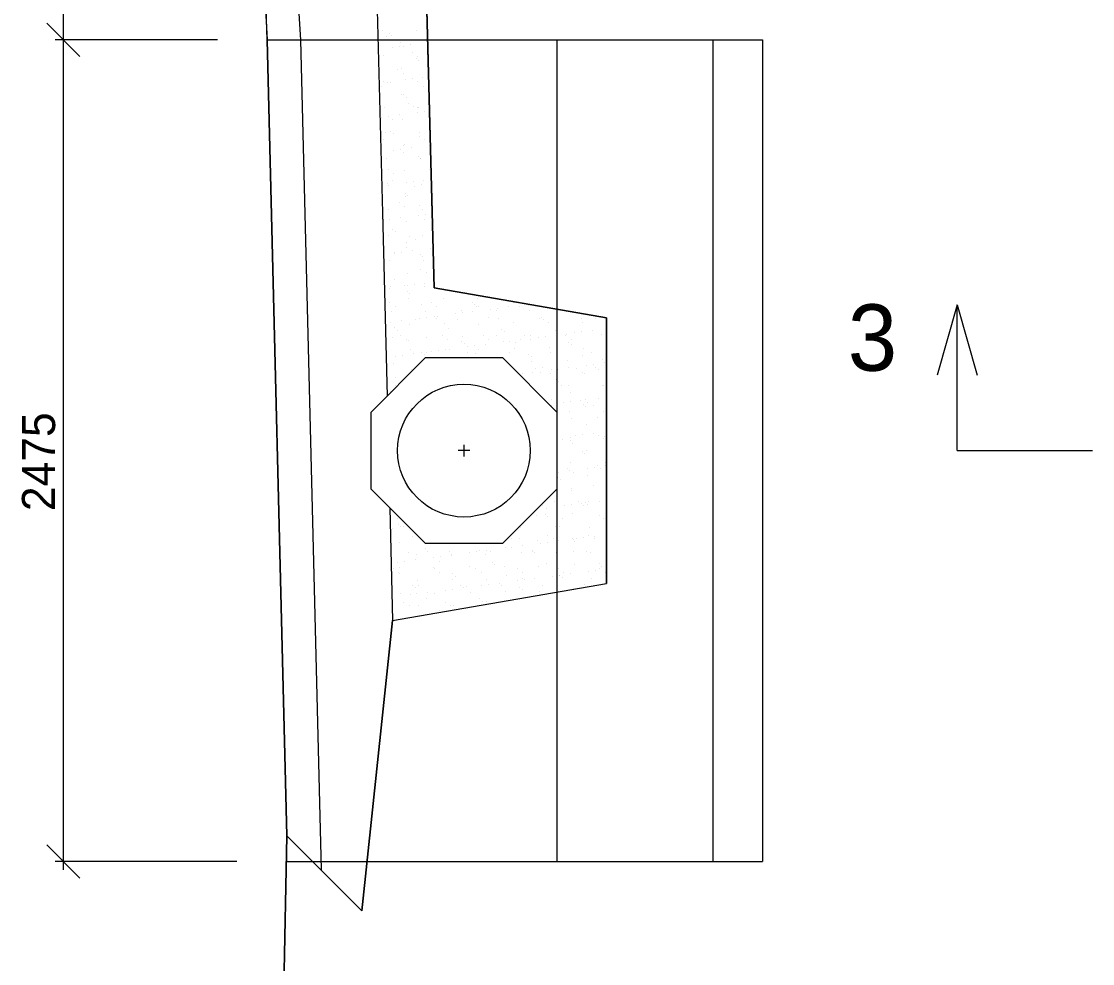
# Model space of a CAD drawing. Extents: x -2363 to 18637, y 14070 to 28920.
# Drawn here: x -595 to 2634, y 19057 to 21895 of the extents above; entities that cross this region are included whole.
import ezdxf

# ---------------------------------------------------------------- set-up
doc = ezdxf.new("R2010")
doc.units = 0
for name, color, linetype in [('KÓTY', 7, 'Continuous'), ('OBRYS', 7, 'Continuous'), ('SJEZD', 7, 'Continuous'), ('ŠRAFY', 7, 'Continuous')]:
    doc.layers.add(name, color=color, linetype=linetype)

# ---------------------------------------------------------------- blocks, each defined once
blk = doc.blocks.new('_ARCHTICK')
blk.add_lwpolyline([(-0.5, -0.5), (0.5, 0.5)])

msp = doc.modelspace()

# ---------------------------------------------------------------- linework, layer by layer
at = {"layer": 'KÓTY'}
for p, q in [((-468.1, 21814.7), (-468.1, 22364.7)), ((-468.1, 19339.7), (-468.1, 21864.7)), ((-3.8, 21839.7), (-493.1, 21839.7)), ((-3.8, 21839.7), (-493.1, 21839.7)), ((2225.7, 21041.5), (2165.7, 20829)), ((2225.7, 20602.2), (2225.7, 21041.5)), ((2225.7, 21041.5), (2285.7, 20829)), ((2225.7, 20602.2), (2633.8, 20602.2)), ((54.3, 19364.7), (-493.1, 19364.7))]:
    msp.add_line(p, q, dxfattribs=at)
at = {"layer": 'OBRYS'}
for p, q in [((649.6, 21092.9), (495.9, 26839.7)), ((146.2, 21839.7), (35.9, 25339.7)), ((205.8, 19441.7), (146.2, 21839.7)), ((1169.1, 21002.2), (649.6, 21092.9)), ((1169.1, 20202.2), (1169.1, 21002.2)), ((524.1, 20090.3), (1169.1, 20202.2)), ((431.3, 19216.3), (524.1, 20090.3)), ((175.8, 17970), (205.8, 19441.7)), ((205.8, 19441.7), (431.3, 19216.3))]:
    msp.add_line(p, q, dxfattribs=at)
msp.add_circle((739.1, 20602.2), 200, dxfattribs=at)
at = {"layer": 'SJEZD'}
for p, q in [((495.9, 26839.7), (649.6, 21092.9)), ((375.9, 25715.5), (493.5, 21318.7)), ((216.1, 22342), (246.2, 21839.7)), ((116.2, 22339.7), (146.2, 21839.7)), ((146.2, 21839.7), (205.8, 19441.7)), ((146.2, 21839.7), (1639.1, 21839.7)), ((246.2, 21839.7), (308.4, 19339.2)), ((1019.1, 21839.7), (1019.1, 19364.7)), ((1489.1, 21839.7), (1489.1, 19364.7)), ((1639.1, 21839.7), (1639.1, 19364.7)), ((493.5, 21318.7), (507.3, 20766.3)), ((649.6, 21092.9), (1169.1, 21002.2)), ((1169.1, 21002.2), (1169.1, 20202.2)), ((459.1, 20718.2), (623.2, 20882.2)), ((623.2, 20882.2), (855.1, 20882.2)), ((855.1, 20882.2), (1019.1, 20718.2)), ((459.1, 20486.3), (459.1, 20718.2)), ((1019.1, 20718.2), (1019.1, 20486.3)), ((756.5, 20602.2), (721.8, 20602.2)), ((739.1, 20619.6), (739.1, 20584.9)), ((623.2, 20322.2), (459.1, 20486.3)), ((1019.1, 20486.3), (855.1, 20322.2)), ((515.6, 20429.8), (524.1, 20090.3)), ((855.1, 20322.2), (623.2, 20322.2)), ((524.1, 20090.3), (1169.1, 20202.2)), ((524.1, 20090.3), (431.3, 19216.3)), ((205.8, 19441.7), (175.8, 17970)), ((205.8, 19441.7), (431.3, 19216.3)), ((204.3, 19364.7), (1639.1, 19364.7))]:
    msp.add_line(p, q, dxfattribs=at)
msp.add_circle((739.1, 20602.2), 200, dxfattribs=at)
at = {"layer": 'ŠRAFY'}
for p, q in [((493.1, 21868.1), (493.1, 21868.1)), ((513.8, 21859), (513.8, 21859)), ((595.4, 21867.6), (595.4, 21867.6)), ((506.8, 21849.6), (506.8, 21849.6)), ((521.1, 21852.2), (521.1, 21852.2)), ((523.7, 21838.8), (523.7, 21838.8)), ((547.2, 21830.6), (547.2, 21830.6)), ((578.4, 21825), (578.4, 21825)), ((525.1, 21818), (525.1, 21818)), ((545.9, 21820.7), (545.9, 21820.7)), ((555.9, 21820.4), (555.9, 21820.4)), ((584.4, 21800.1), (584.4, 21800.1)), ((495.6, 21791), (495.6, 21791)), ((595.8, 21783.9), (595.8, 21783.9)), ((597.9, 21790.5), (597.9, 21790.5)), ((603.1, 21777.1), (603.1, 21777.1)), ((482.9, 21742), (482.9, 21742)), ((539.1, 21749.4), (539.1, 21749.4)), ((549.7, 21753.5), (549.7, 21753.5)), ((556, 21738.7), (556, 21738.7)), ((492.1, 21699.8), (492.1, 21699.8)), ((498.1, 21714), (498.1, 21714)), ((507.6, 21712.1), (507.6, 21712.1)), ((517.7, 21710.1), (517.7, 21710.1)), ((562, 21719.3), (562, 21719.3)), ((582.8, 21722), (582.8, 21722)), ((600.4, 21713.5), (600.4, 21713.5)), ((615.3, 21726.3), (615.3, 21726.3)), ((616.7, 21700), (616.7, 21700)), ((552.2, 21676.4), (552.2, 21676.4)), ((557.5, 21673.6), (557.5, 21673.6)), ((564.9, 21666.9), (564.9, 21666.9)), ((500.6, 21636.9), (500.6, 21636.9)), ((571.4, 21649.3), (571.4, 21649.3)), ((588.3, 21638.5), (588.3, 21638.5)), ((599.7, 21635), (599.7, 21635)), ((603, 21636.4), (603, 21636.4)), ((491.2, 21606.4), (491.2, 21606.4)), ((512, 21609.1), (512, 21609.1)), ((524.4, 21599.6), (524.4, 21599.6)), ((544.5, 21613.4), (544.5, 21613.4)), ((554.7, 21599.4), (554.7, 21599.4)), ((598.8, 21620.6), (598.8, 21620.6)), ((619.7, 21623.3), (619.7, 21623.3)), ((496, 21538.1), (496, 21538.1)), ((503.2, 21559.8), (503.2, 21559.8)), ((519.2, 21563.4), (519.2, 21563.4)), ((526.6, 21556.6), (526.6, 21556.6)), ((603.7, 21549.1), (603.7, 21549.1)), ((605.5, 21559.3), (605.5, 21559.3)), ((620.6, 21538.3), (620.6, 21538.3)), ((528, 21507.7), (528, 21507.7)), ((548.9, 21510.4), (548.9, 21510.4)), ((557.2, 21522.3), (557.2, 21522.3)), ((561.4, 21524.8), (561.4, 21524.8)), ((581.4, 21514.7), (581.4, 21514.7)), ((635.7, 21521.9), (635.7, 21521.9)), ((505.7, 21482.7), (505.7, 21482.7)), ((556.7, 21499.4), (556.7, 21499.4)), ((601.2, 21488.3), (601.2, 21488.3)), ((608, 21482.2), (608, 21482.2)), ((608.6, 21481.5), (608.6, 21481.5)), ((511.4, 21448.7), (511.4, 21448.7)), ((528.3, 21438), (528.3, 21438)), ((559.8, 21445.2), (559.8, 21445.2)), ((636, 21448.9), (636, 21448.9)), ((508.2, 21405.7), (508.2, 21405.7)), ((523.2, 21414.5), (523.2, 21414.5)), ((564.9, 21409), (564.9, 21409)), ((585.7, 21411.7), (585.7, 21411.7)), ((610.5, 21405.2), (610.5, 21405.2)), ((618.3, 21416), (618.3, 21416)), ((510.6, 21401.8), (510.6, 21401.8)), ((563, 21378), (563, 21378)), ((589, 21399.3), (589, 21399.3)), ((543.7, 21348.5), (543.7, 21348.5)), ((562.3, 21368.2), (562.3, 21368.2)), ((570.3, 21371.3), (570.3, 21371.3)), ((510.7, 21328.6), (510.7, 21328.6)), ((560.6, 21337.8), (560.6, 21337.8)), ((601.8, 21310.3), (601.8, 21310.3)), ((605.1, 21339.4), (605.1, 21339.4)), ((613, 21328.1), (613, 21328.1)), ((622.6, 21313), (622.6, 21313)), ((494.1, 21296.1), (494.1, 21296.1)), ((496.8, 21298.9), (496.8, 21298.9)), ((515, 21298.8), (515, 21298.8)), ((547.5, 21303.1), (547.5, 21303.1)), ((564.8, 21291.1), (564.8, 21291.1)), ((621.3, 21299.1), (621.3, 21299.1)), ((513.2, 21251.5), (513.2, 21251.5)), ((524.7, 21267.8), (524.7, 21267.8)), ((532.1, 21261.1), (532.1, 21261.1)), ((576.1, 21248.4), (576.1, 21248.4)), ((615.6, 21251), (615.6, 21251)), ((566.9, 21229.2), (566.9, 21229.2)), ((567.3, 21214), (567.3, 21214)), ((592.9, 21237.6), (592.9, 21237.6)), ((638.7, 21211.6), (638.7, 21211.6)), ((529.1, 21198.7), (529.1, 21198.7)), ((531, 21197.4), (531, 21197.4)), ((551.8, 21200.1), (551.8, 21200.1)), ((584.3, 21204.4), (584.3, 21204.4)), ((606.7, 21192.7), (606.7, 21192.7)), ((614.1, 21185.9), (614.1, 21185.9)), ((515.8, 21174.4), (515.8, 21174.4)), ((608.4, 21148.2), (608.4, 21148.2)), ((618.1, 21173.9), (618.1, 21173.9)), ((500.7, 21137.2), (500.7, 21137.2)), ((528.6, 21118.9), (528.6, 21118.9)), ((569.8, 21136.9), (569.8, 21136.9)), ((625.2, 21137.5), (625.2, 21137.5)), ((513.6, 21091.5), (513.6, 21091.5)), ((518.3, 21097.4), (518.3, 21097.4)), ((561.4, 21098.5), (561.4, 21098.5)), ((567.9, 21098.7), (567.9, 21098.7)), ((568.4, 21082.5), (568.4, 21082.5)), ((588.7, 21101.4), (588.7, 21101.4)), ((620.6, 21096.9), (620.6, 21096.9)), ((621.2, 21105.7), (621.2, 21105.7)), ((572.4, 21059.9), (572.4, 21059.9)), ((575.8, 21075.7), (575.8, 21075.7)), ((677.1, 21061.2), (677.1, 21061.2)), ((779.4, 21060.7), (779.4, 21060.7)), ((516.1, 21047.8), (516.1, 21047.8)), ((520.8, 21020.3), (520.8, 21020.3)), ((533, 21037.1), (533, 21037.1)), ((610.6, 21043.8), (610.6, 21043.8)), ((623.1, 21019.8), (623.1, 21019.8)), ((640.7, 21048), (640.7, 21048)), ((657.5, 21037.3), (657.5, 21037.3)), ((731.2, 21023.7), (731.2, 21023.7)), ((733.3, 21016.9), (733.3, 21016.9)), ((765.2, 21048.3), (765.2, 21048.3)), ((765.8, 21021.2), (765.8, 21021.2)), ((770.7, 21042.4), (770.7, 21042.4)), ((778, 21035.7), (778, 21035.7)), ((782.1, 21037.5), (782.1, 21037.5)), ((820.1, 21028.3), (820.1, 21028.3)), ((835.9, 21025), (835.9, 21025)), ((840.9, 21031), (840.9, 21031)), ((873.5, 21035.3), (873.5, 21035.3)), ((889.8, 21048.5), (889.8, 21048.5)), ((906.7, 21037.7), (906.7, 21037.7)), ((927.8, 21042.5), (927.8, 21042.5)), ((933.1, 21038.9), (933.1, 21038.9)), ((938.2, 21024.5), (938.2, 21024.5)), ((517.9, 20988.5), (517.9, 20988.5)), ((550.4, 20992.8), (550.4, 20992.8)), ((593.7, 20998.4), (593.7, 20998.4)), ((604.8, 21000), (604.8, 21000)), ((625.6, 21002.7), (625.6, 21002.7)), ((650.4, 21007.3), (650.4, 21007.3)), ((657.8, 21000.6), (657.8, 21000.6)), ((658.1, 21007), (658.1, 21007)), ((712.4, 21014.1), (712.4, 21014.1)), ((718.3, 20998.6), (718.3, 20998.6)), ((812.8, 21003.8), (812.8, 21003.8)), ((842.8, 20998.8), (842.8, 20998.8)), ((889.9, 20987.5), (889.9, 20987.5)), ((967.4, 20999.1), (967.4, 20999.1)), ((972.9, 21002.4), (972.9, 21002.4)), ((980.3, 20995.7), (980.3, 20995.7)), ((994.7, 20988.9), (994.7, 20988.9)), ((1092, 20999.3), (1092, 20999.3)), ((1097, 20988.4), (1097, 20988.4)), ((1135.3, 20998.9), (1135.3, 20998.9)), ((530.2, 20972.2), (530.2, 20972.2)), ((537.5, 20965.5), (537.5, 20965.5)), ((574.9, 20982.8), (574.9, 20982.8)), ((679.6, 20984.1), (679.6, 20984.1)), ((692.6, 20968.7), (692.6, 20968.7)), ((781.9, 20983.6), (781.9, 20983.6)), ((852.6, 20967.3), (852.6, 20967.3)), ((860, 20960.6), (860, 20960.6)), ((1015.1, 20963.8), (1015.1, 20963.8)), ((1072.3, 20957.9), (1072.3, 20957.9)), ((1093.2, 20960.7), (1093.2, 20960.7)), ((1125.7, 20965), (1125.7, 20965)), ((1153.4, 20952.7), (1153.4, 20952.7)), ((523.3, 20943.2), (523.3, 20943.2)), ((548.4, 20947.7), (548.4, 20947.7)), ((565.3, 20936.9), (565.3, 20936.9)), ((572.3, 20933.6), (572.3, 20933.6)), ((625.6, 20942.7), (625.6, 20942.7)), ((673, 20947.9), (673, 20947.9)), ((689.8, 20937.1), (689.8, 20937.1)), ((732.4, 20932.2), (732.4, 20932.2)), ((733.7, 20946.6), (733.7, 20946.6)), ((739.8, 20925.4), (739.8, 20925.4)), ((797.5, 20948.1), (797.5, 20948.1)), ((802.7, 20922.4), (802.7, 20922.4)), ((814.4, 20937.4), (814.4, 20937.4)), ((838.4, 20948), (838.4, 20948)), ((857, 20929.6), (857, 20929.6)), ((877.8, 20932.3), (877.8, 20932.3)), ((894.8, 20928.7), (894.8, 20928.7)), ((910.3, 20936.6), (910.3, 20936.6)), ((922.1, 20948.3), (922.1, 20948.3)), ((939, 20937.6), (939, 20937.6)), ((940.7, 20947.5), (940.7, 20947.5)), ((964.7, 20943.8), (964.7, 20943.8)), ((985.5, 20946.5), (985.5, 20946.5)), ((1018, 20950.8), (1018, 20950.8)), ((1046.7, 20948.6), (1046.7, 20948.6)), ((1048.7, 20951.4), (1048.7, 20951.4)), ((1054.9, 20927.3), (1054.9, 20927.3)), ((1062.2, 20920.5), (1062.2, 20920.5)), ((1063.5, 20937.8), (1063.5, 20937.8)), ((554.8, 20889.8), (554.8, 20889.8)), ((577.4, 20905.7), (577.4, 20905.7)), ((587.3, 20894.1), (587.3, 20894.1)), ((612.2, 20897.1), (612.2, 20897.1)), ((619.5, 20890.3), (619.5, 20890.3)), ((626, 20898.2), (626, 20898.2)), ((641.6, 20901.2), (641.6, 20901.2)), ((662.5, 20904), (662.5, 20904)), ((682.1, 20907.1), (682.1, 20907.1)), ((695, 20908.3), (695, 20908.3)), ((749.3, 20915.4), (749.3, 20915.4)), ((750.6, 20898.4), (750.6, 20898.4)), ((770.1, 20918.2), (770.1, 20918.2)), ((774.6, 20893.6), (774.6, 20893.6)), ((784.4, 20906.6), (784.4, 20906.6)), ((875.1, 20898.7), (875.1, 20898.7)), ((892.5, 20910.5), (892.5, 20910.5)), ((934.6, 20892.2), (934.6, 20892.2)), ((997.2, 20911.8), (997.2, 20911.8)), ((999.7, 20898.9), (999.7, 20898.9)), ((1097, 20888.6), (1097, 20888.6)), ((1099.5, 20911.3), (1099.5, 20911.3)), ((1124.3, 20899.1), (1124.3, 20899.1)), ((525.8, 20866.1), (525.8, 20866.1)), ((534, 20887.1), (534, 20887.1)), ((942, 20885.4), (942, 20885.4)), ((943.2, 20870.4), (943.2, 20870.4)), ((1051.3, 20874.3), (1051.3, 20874.3)), ((1109.2, 20859.2), (1109.2, 20859.2)), ((1130, 20862), (1130, 20862)), ((1156, 20875.6), (1156, 20875.6)), ((1162.6, 20866.3), (1162.6, 20866.3)), ((534.1, 20823.3), (534.1, 20823.3)), ((580.7, 20847.5), (580.7, 20847.5)), ((914.7, 20833.6), (914.7, 20833.6)), ((947.2, 20837.9), (947.2, 20837.9)), ((954.4, 20848.2), (954.4, 20848.2)), ((971.3, 20837.4), (971.3, 20837.4)), ((976.8, 20853.5), (976.8, 20853.5)), ((999.7, 20834.7), (999.7, 20834.7)), ((1001.5, 20845.1), (1001.5, 20845.1)), ((1022.4, 20847.8), (1022.4, 20847.8)), ((1054.9, 20852.1), (1054.9, 20852.1)), ((1079, 20848.4), (1079, 20848.4)), ((1095.8, 20837.6), (1095.8, 20837.6)), ((1102, 20834.2), (1102, 20834.2)), ((1136.9, 20852.2), (1136.9, 20852.2)), ((1144.2, 20845.4), (1144.2, 20845.4)), ((533.7, 20797.8), (533.7, 20797.8)), ((945.7, 20793.3), (945.7, 20793.3)), ((1016.6, 20817.1), (1016.6, 20817.1)), ((1024, 20810.3), (1024, 20810.3)), ((1032, 20798.7), (1032, 20798.7)), ((1053.8, 20797.2), (1053.8, 20797.2)), ((1156.6, 20799), (1156.6, 20799)), ((1158.5, 20798.5), (1158.5, 20798.5)), ((516.5, 20781.2), (516.5, 20781.2)), ((528.4, 20789.1), (528.4, 20789.1)), ((1058.8, 20778.4), (1058.8, 20778.4)), ((1146.1, 20760.5), (1146.1, 20760.5)), ((1166.9, 20763.3), (1166.9, 20763.3)), ((1002.2, 20757.6), (1002.2, 20757.6)), ((1003.6, 20737.3), (1003.6, 20737.3)), ((1038.4, 20746.3), (1038.4, 20746.3)), ((1059.2, 20749.1), (1059.2, 20749.1)), ((1091.8, 20753.4), (1091.8, 20753.4)), ((1098.6, 20741.9), (1098.6, 20741.9)), ((1104.5, 20757.2), (1104.5, 20757.2)), ((1106, 20735.2), (1106, 20735.2)), ((1111.3, 20748.2), (1111.3, 20748.2)), ((1128.1, 20737.5), (1128.1, 20737.5)), ((1056.3, 20720.1), (1056.3, 20720.1)), ((1064.3, 20698.6), (1064.3, 20698.6)), ((1140.8, 20703.3), (1140.8, 20703.3)), ((1161, 20721.5), (1161, 20721.5)), ((1020.5, 20668.2), (1020.5, 20668.2)), ((1107.1, 20680.1), (1107.1, 20680.1)), ((1021, 20640.5), (1021, 20640.5)), ((1035.9, 20637.1), (1035.9, 20637.1)), ((1058.8, 20643.1), (1058.8, 20643.1)), ((1060.3, 20631.7), (1060.3, 20631.7)), ((1075.3, 20647.6), (1075.3, 20647.6)), ((1096.1, 20650.4), (1096.1, 20650.4)), ((1128.6, 20654.7), (1128.6, 20654.7)), ((1143.6, 20648.1), (1143.6, 20648.1)), ((1160.4, 20637.3), (1160.4, 20637.3)), ((1163.5, 20644.4), (1163.5, 20644.4)), ((1067.7, 20624.9), (1067.7, 20624.9)), ((1096.6, 20598.4), (1096.6, 20598.4)), ((1109.6, 20603), (1109.6, 20603)), ((1061.3, 20566), (1061.3, 20566)), ((1102.5, 20593.1), (1102.5, 20593.1)), ((1166, 20567.3), (1166, 20567.3)), ((1025.3, 20537.5), (1025.3, 20537.5)), ((1051.3, 20547.7), (1051.3, 20547.7)), ((1057.9, 20541.8), (1057.9, 20541.8)), ((1068.2, 20536.9), (1068.2, 20536.9)), ((1112.2, 20548.9), (1112.2, 20548.9)), ((1133, 20551.7), (1133, 20551.7)), ((1142.3, 20556.6), (1142.3, 20556.6)), ((1149.7, 20549.8), (1149.7, 20549.8)), ((1165.5, 20556), (1165.5, 20556)), ((1022.1, 20521.5), (1022.1, 20521.5)), ((1029.5, 20514.7), (1029.5, 20514.7)), ((1112.1, 20525.9), (1112.1, 20525.9)), ((1063.9, 20488.9), (1063.9, 20488.9)), ((1064.3, 20482.8), (1064.3, 20482.8)), ((1128.9, 20498.2), (1128.9, 20498.2)), ((1168.6, 20490.3), (1168.6, 20490.3)), ((975.9, 20436.5), (975.9, 20436.5)), ((1012.3, 20449.4), (1012.3, 20449.4)), ((1041.4, 20436), (1041.4, 20436)), ((1062.2, 20438.8), (1062.2, 20438.8)), ((1083.6, 20447.5), (1083.6, 20447.5)), ((1094.7, 20443.1), (1094.7, 20443.1)), ((1100.5, 20436.8), (1100.5, 20436.8)), ((1104.1, 20446.3), (1104.1, 20446.3)), ((1111.4, 20439.6), (1111.4, 20439.6)), ((1114.6, 20448.9), (1114.6, 20448.9)), ((1149.1, 20450.2), (1149.1, 20450.2)), ((541, 20403.7), (541, 20403.7)), ((958.3, 20408), (958.3, 20408)), ((983.8, 20411.2), (983.8, 20411.2)), ((987.1, 20428.9), (987.1, 20428.9)), ((991.2, 20404.5), (991.2, 20404.5)), ((1066.4, 20411.8), (1066.4, 20411.8)), ((1146.2, 20407.7), (1146.2, 20407.7)), ((538.4, 20396.9), (538.4, 20396.9)), ((541.1, 20381), (541.1, 20381)), ((548.5, 20374.3), (548.5, 20374.3)), ((556.4, 20372.2), (556.4, 20372.2)), ((910.1, 20370.9), (910.1, 20370.9)), ((1014.8, 20372.3), (1014.8, 20372.3)), ((1026, 20372.6), (1026, 20372.6)), ((1036.7, 20397.9), (1036.7, 20397.9)), ((1117.1, 20371.8), (1117.1, 20371.8)), ((1161.2, 20398.1), (1161.2, 20398.1)), ((523.9, 20367.9), (523.9, 20367.9)), ((583.3, 20342.4), (583.3, 20342.4)), ((991.4, 20347.1), (991.4, 20347.1)), ((1099.1, 20340.1), (1099.1, 20340.1)), ((1115.9, 20347.3), (1115.9, 20347.3)), ((1131.6, 20344.4), (1131.6, 20344.4)), ((543.5, 20326.6), (543.5, 20326.6)), ((862.9, 20309), (862.9, 20309)), ((883.7, 20336.1), (883.7, 20336.1)), ((883.7, 20311.7), (883.7, 20311.7)), ((905.7, 20337.5), (905.7, 20337.5)), ((916.3, 20316), (916.3, 20316)), ((960.9, 20330.9), (960.9, 20330.9)), ((970.6, 20323.2), (970.6, 20323.2)), ((991.4, 20325.9), (991.4, 20325.9)), ((1008.2, 20336.4), (1008.2, 20336.4)), ((1023.9, 20330.2), (1023.9, 20330.2)), ((1065.8, 20336.1), (1065.8, 20336.1)), ((1068.9, 20334.8), (1068.9, 20334.8)), ((1073.2, 20329.4), (1073.2, 20329.4)), ((1078.3, 20337.3), (1078.3, 20337.3)), ((1132.8, 20336.6), (1132.8, 20336.6)), ((570.7, 20296.8), (570.7, 20296.8)), ((597.6, 20289.1), (597.6, 20289.1)), ((623.1, 20305.9), (623.1, 20305.9)), ((630.5, 20299.2), (630.5, 20299.2)), ((647.6, 20280.6), (647.6, 20280.6)), ((668.4, 20283.4), (668.4, 20283.4)), ((695.3, 20297), (695.3, 20297)), ((700.9, 20287.7), (700.9, 20287.7)), ((702.3, 20290.5), (702.3, 20290.5)), ((755.3, 20294.8), (755.3, 20294.8)), ((776.1, 20297.5), (776.1, 20297.5)), ((785.5, 20302.4), (785.5, 20302.4)), ((804.6, 20290), (804.6, 20290)), ((808.6, 20301.8), (808.6, 20301.8)), ((819.8, 20297.2), (819.8, 20297.2)), ((912.6, 20293.9), (912.6, 20293.9)), ((944.4, 20297.5), (944.4, 20297.5)), ((945.6, 20301), (945.6, 20301)), ((952.9, 20294.2), (952.9, 20294.2)), ((1017.3, 20295.2), (1017.3, 20295.2)), ((1069, 20297.7), (1069, 20297.7)), ((1108, 20297.5), (1108, 20297.5)), ((1119.7, 20294.7), (1119.7, 20294.7)), ((525.4, 20246), (525.4, 20246)), ((539.9, 20266.5), (539.9, 20266.5)), ((546, 20249.6), (546, 20249.6)), ((560.7, 20269.2), (560.7, 20269.2)), ((593.3, 20273.5), (593.3, 20273.5)), ((648.3, 20249.1), (648.3, 20249.1)), ((650, 20246.3), (650, 20246.3)), ((665.3, 20267.3), (665.3, 20267.3)), ((756.4, 20253), (756.4, 20253)), ((774.5, 20246.5), (774.5, 20246.5)), ((825.3, 20265.9), (825.3, 20265.9)), ((832.7, 20259.1), (832.7, 20259.1)), ((861.1, 20254.3), (861.1, 20254.3)), ((899.1, 20246.7), (899.1, 20246.7)), ((963.4, 20253.8), (963.4, 20253.8)), ((987.7, 20262.4), (987.7, 20262.4)), ((1023.7, 20247), (1023.7, 20247)), ((1071.4, 20257.7), (1071.4, 20257.7)), ((1147.8, 20261), (1147.8, 20261)), ((1148.2, 20247.2), (1148.2, 20247.2)), ((1155.2, 20254.2), (1155.2, 20254.2)), ((1168.5, 20245.6), (1168.5, 20245.6)), ((542.3, 20235.3), (542.3, 20235.3)), ((545, 20232.2), (545, 20232.2)), ((600.1, 20212.1), (600.1, 20212.1)), ((666.8, 20235.5), (666.8, 20235.5)), ((704.8, 20213.4), (704.8, 20213.4)), ((705.1, 20230.8), (705.1, 20230.8)), ((712.4, 20224), (712.4, 20224)), ((791.4, 20235.8), (791.4, 20235.8)), ((807.1, 20212.9), (807.1, 20212.9)), ((867.5, 20227.3), (867.5, 20227.3)), ((899.8, 20210.3), (899.8, 20210.3)), ((915.1, 20216.8), (915.1, 20216.8)), ((916, 20236), (916, 20236)), ((920.6, 20213), (920.6, 20213)), ((953.1, 20217.3), (953.1, 20217.3)), ((1007.5, 20224.4), (1007.5, 20224.4)), ((1019.8, 20218.1), (1019.8, 20218.1)), ((1027.5, 20225.9), (1027.5, 20225.9)), ((1028.3, 20227.2), (1028.3, 20227.2)), ((1034.9, 20219.1), (1034.9, 20219.1)), ((1040.5, 20236.2), (1040.5, 20236.2)), ((1060.8, 20231.5), (1060.8, 20231.5)), ((1115.2, 20238.6), (1115.2, 20238.6)), ((1122.2, 20217.6), (1122.2, 20217.6)), ((1136, 20241.4), (1136, 20241.4)), ((1165.1, 20236.4), (1165.1, 20236.4)), ((584.8, 20195.7), (584.8, 20195.7)), ((592.2, 20188.9), (592.2, 20188.9)), ((603, 20196.6), (603, 20196.6)), ((684.5, 20181.9), (684.5, 20181.9)), ((705.3, 20184.7), (705.3, 20184.7)), ((727.6, 20196.8), (727.6, 20196.8)), ((737.8, 20188.9), (737.8, 20188.9)), ((747.2, 20192.1), (747.2, 20192.1)), ((792.1, 20196.1), (792.1, 20196.1)), ((813, 20198.8), (813, 20198.8)), ((845.5, 20203.1), (845.5, 20203.1)), ((852.1, 20197.1), (852.1, 20197.1)), ((863.6, 20177.2), (863.6, 20177.2)), ((907.3, 20190.8), (907.3, 20190.8)), ((914.7, 20184), (914.7, 20184)), ((976.7, 20197.3), (976.7, 20197.3)), ((1069.7, 20187.2), (1069.7, 20187.2)), ((1101.3, 20197.5), (1101.3, 20197.5)), ((522.5, 20160.6), (522.5, 20160.6)), ((548.5, 20172.5), (548.5, 20172.5)), ((557.7, 20145.9), (557.7, 20145.9)), ((576.8, 20167.7), (576.8, 20167.7)), ((597.6, 20170.5), (597.6, 20170.5)), ((627, 20157), (627, 20157)), ((630.1, 20174.8), (630.1, 20174.8)), ((650.8, 20172), (650.8, 20172)), ((682.3, 20146.1), (682.3, 20146.1)), ((758.9, 20175.9), (758.9, 20175.9)), ((787.1, 20155.7), (787.1, 20155.7)), ((794.4, 20148.9), (794.4, 20148.9)), ((806.8, 20146.3), (806.8, 20146.3)), ((965.9, 20176.7), (965.9, 20176.7)), ((574.6, 20135.1), (574.6, 20135.1)), ((602.6, 20135), (602.6, 20135)), ((666.8, 20120.6), (666.8, 20120.6)), ((699.1, 20135.4), (699.1, 20135.4)), ((707.3, 20136.3), (707.3, 20136.3)), ((551, 20095.4), (551, 20095.4))]:
    msp.add_line(p, q, dxfattribs=at)

# ---------------------------------------------------------------- block references
at = {"layer": 'KÓTY', "xscale": 100, "yscale": 100}
for p, rotation in [((-468.1, 21839.7), 90), ((-468.1, 21839.7), -90.00000000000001), ((-468.1, 19364.7), -90.00000000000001)]:
    msp.add_blockref('_ARCHTICK', p, dxfattribs=dict(at, rotation=rotation))

# ---------------------------------------------------------------- texts
at = {"layer": 'KÓTY'}
msp.add_text('3', height=200, dxfattribs=at).set_placement((1896, 20842.8))
msp.add_text('2475', height=100, rotation=90, dxfattribs=at).set_placement((-493.1, 20420))

doc.saveas('drawing.dxf')
